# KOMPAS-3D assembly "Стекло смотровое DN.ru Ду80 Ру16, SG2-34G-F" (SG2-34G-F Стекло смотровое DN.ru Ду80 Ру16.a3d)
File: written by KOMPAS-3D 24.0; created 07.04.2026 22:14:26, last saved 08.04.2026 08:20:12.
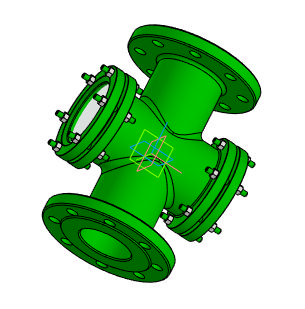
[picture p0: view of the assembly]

Document properties: Автор: Main; Полное имя файла: D:\DN.ru Аутсерс\Стекло смотровое DN.ru\Исходники\Стекло смотровое DN.ru SG2-34G-F тип В ГОСТ 21836-2021 Ду80 Ру16, углеродистая сталь, фланцевое\SG2-34G-F Стекло смотровое DN.ru Ду80 Ру16.a3d

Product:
- Component [detail]: Деталь  | qty 1  | pos. 1  | Масса: 18.583108; Автор: Main; additional columns: Типовые; source file: ДетальДеталь_1.m3d
- Component [detail]: Стекло  | qty 2  | pos. 2  | Масса: 0.680252; Автор: Main; source file: СтеклоСтекло_1.m3d
- Component [detail]: ANSI B18.2.4.2M - M8x1,25 - 13  | designation ANSI B18.2.4.2M - M8x1,25  | qty 24  | pos. 3  | Масса: 0.006562; Комментарий: Типы метрических   шестигранных гаек   2; Автор: Main; additional columns: Сталь, мягкая; source file: ANSI B18.2.4.2M - M8x1,25ANSI B18.2.4.2M - M8x1,25 - 13_1.m3d
- Part/product: Стекло смотровое DN.ru Ду80 Ру16  | designation SG2-34G-F
    Масса: 20.5
    Раздел спецификации: Прочие изделия
    Примечание: D500-00086

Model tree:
1. Массив по концентрической сетке:1  (labels: Грань.Твердое тело1; Грань.Solid1; Ребро.Твердое тело1; Ребро.Solid1)  (6 pattern instances)
     Шаг 2 = 360

Expressions: SG2-34G-F
Referenced files in D:\DN.ru Аутсерс\Стекло смотровое DN.ru\Исходники\Стекло смотровое DN.ru SG2-34G-F тип В ГОСТ 21836-2021 Ду80 Ру16, углеродистая сталь, фланцевое\: ДетальДеталь_1.m3d, СтеклоСтекло_1.m3d, ANSI B18.2.4.2M - M8x1,25ANSI B18.2.4.2M - M8x1,25 - 13_1.m3d
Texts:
  Стекло Стекло (1)
  Стекло Стекло (2)
  ANSI B18.2.4.2M - M8x1,25 ANSI B18.2.4.2M - M8x1,25 - 13 (1)
  ANSI B18.2.4.2M - M8x1,25 ANSI B18.2.4.2M - M8x1,25 - 13 (2)
  ANSI B18.2.4.2M - M8x1,25 ANSI B18.2.4.2M - M8x1,25 - 13 (3)
  ANSI B18.2.4.2M - M8x1,25 ANSI B18.2.4.2M - M8x1,25 - 13 (4)
  ANSI B18.2.4.2M - M8x1,25 ANSI B18.2.4.2M - M8x1,25 - 13 (5)
  ANSI B18.2.4.2M - M8x1,25 ANSI B18.2.4.2M - M8x1,25 - 13 (6)
  ANSI B18.2.4.2M - M8x1,25 ANSI B18.2.4.2M - M8x1,25 - 13 (7)
  ANSI B18.2.4.2M - M8x1,25 ANSI B18.2.4.2M - M8x1,25 - 13 (8)
  ANSI B18.2.4.2M - M8x1,25 ANSI B18.2.4.2M - M8x1,25 - 13 (9)
  ANSI B18.2.4.2M - M8x1,25 ANSI B18.2.4.2M - M8x1,25 - 13 (10)
  ANSI B18.2.4.2M - M8x1,25 ANSI B18.2.4.2M - M8x1,25 - 13 (11)
  ANSI B18.2.4.2M - M8x1,25 ANSI B18.2.4.2M - M8x1,25 - 13 (12)
  ANSI B18.2.4.2M - M8x1,25 ANSI B18.2.4.2M - M8x1,25 - 13 (13)
  ANSI B18.2.4.2M - M8x1,25 ANSI B18.2.4.2M - M8x1,25 - 13 (14)
  ANSI B18.2.4.2M - M8x1,25 ANSI B18.2.4.2M - M8x1,25 - 13 (15)
  ANSI B18.2.4.2M - M8x1,25 ANSI B18.2.4.2M - M8x1,25 - 13 (16)
  ANSI B18.2.4.2M - M8x1,25 ANSI B18.2.4.2M - M8x1,25 - 13 (17)
  ANSI B18.2.4.2M - M8x1,25 ANSI B18.2.4.2M - M8x1,25 - 13 (18)
  ANSI B18.2.4.2M - M8x1,25 ANSI B18.2.4.2M - M8x1,25 - 13 (19)
  ANSI B18.2.4.2M - M8x1,25 ANSI B18.2.4.2M - M8x1,25 - 13 (20)
  ANSI B18.2.4.2M - M8x1,25 ANSI B18.2.4.2M - M8x1,25 - 13 (21)
  ANSI B18.2.4.2M - M8x1,25 ANSI B18.2.4.2M - M8x1,25 - 13 (22)
  ANSI B18.2.4.2M - M8x1,25 ANSI B18.2.4.2M - M8x1,25 - 13 (23)
  ANSI B18.2.4.2M - M8x1,25 ANSI B18.2.4.2M - M8x1,25 - 13 (24)
  Ось Z.Начало координат
  Ось X.Начало координат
